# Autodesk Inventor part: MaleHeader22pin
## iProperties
Shininess: 64.0
Length Units: 11272
Angle Units: 11279
Time Units: 11290
Mass Units: 11286
Length Display Precision: 3
Angle Display Precision: 2
Compacted: True
Part Number: MaleHeader22pin
Document SubType Name: Modeling
Created: 2006-08
Designer: jpalmisano
Manufacturer: Standard
Standards Organization: Custom
Density: 0.0
Volumn: 0.0
Area: 0.0
PropertySet Name: Model Information
Control State: 0
Master: False
Checked Out: False
Author: jpalmisano
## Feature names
1. Extrusion1
2. Extrusion2
